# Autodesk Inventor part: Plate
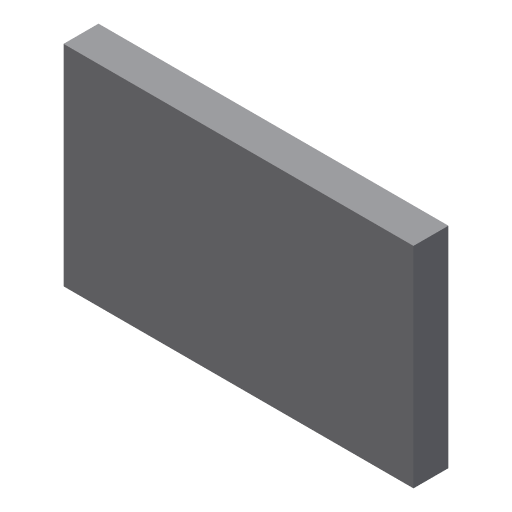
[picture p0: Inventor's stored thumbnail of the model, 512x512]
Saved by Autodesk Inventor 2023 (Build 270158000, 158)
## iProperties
Created: 2009-05
Part Number: Plate
Document SubType Name: Modeling
Designer: Sham
Density: 1 g/cm^3
Material: Generic
Appearance: Default
Author: Sham
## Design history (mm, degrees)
sketch "Sketch1"
  geometry: L1 (12.538, -14.287)-(-37.462, -14.288); L2 (-37.462, -14.288)-(-37.463, 15.712); L3 (-37.463, 15.712)-(12.537, 15.713); L4 (12.537, 15.713)-(12.538, -14.287)
  constraints: 8 end point, 2 parallel, 1 horizontal, 1 perpendicular
  dimensions: "d0" = 50 distance of L1.start L1.end; "d1" = 30 distance of L3.end L1.start
extrude "Extrusion1" new body sketch "Sketch1" distance "d2" = 5; taper "d3" = 0 deg
body "Solid1"
